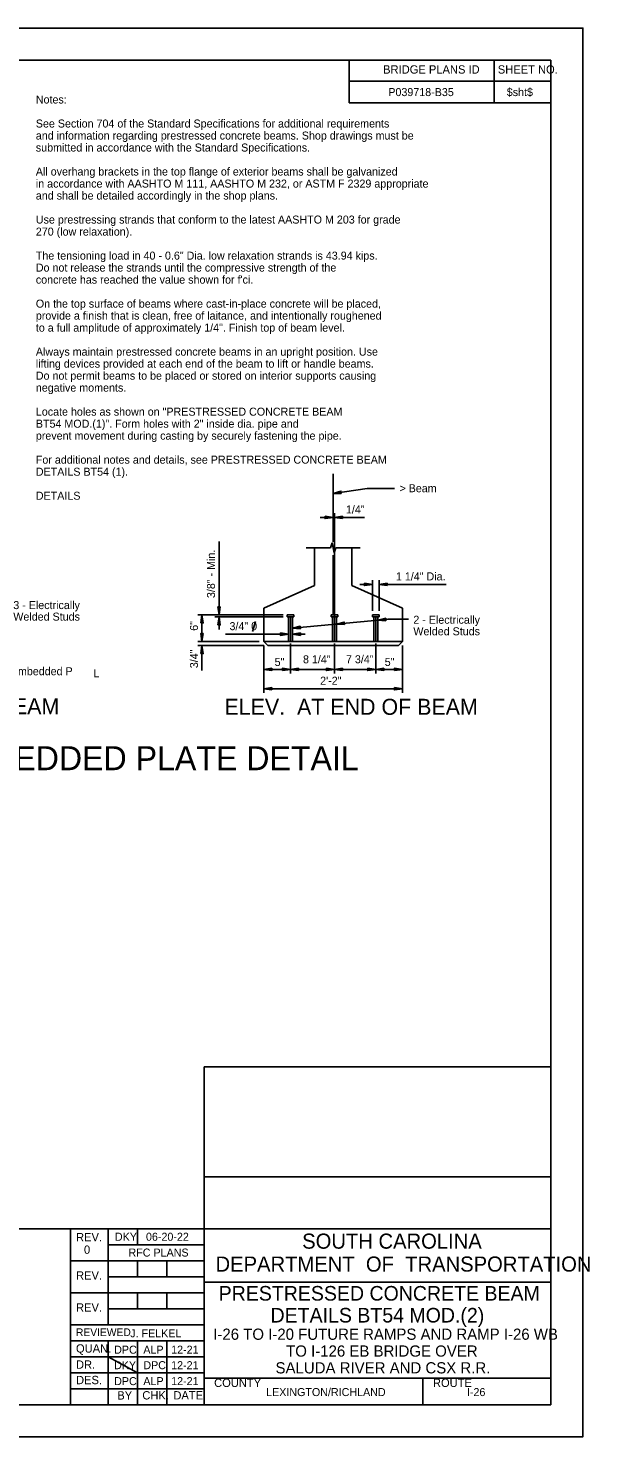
# Model space of a CAD drawing. Extents: x -50.5 to -14.4, y 42.4 to 64.4.
# Drawn here: x -23.18 to -14.41, y 42.45 to 64.45 of the extents above; entities that cross this region are included whole.
import ezdxf

# ---------------------------------------------------------------- set-up
doc = ezdxf.new("R2010")
doc.units = 0
for name, color, linetype in [('BR_AUTO DIMENSION', 7, 'Continuous'), ('BR_BORDER LINES', 7, 'Continuous'), ('BR_CENTER LINES', 7, 'Continuous'), ('BR_PRESTRESSED BEAM', 7, 'Continuous'), ('BR_STRUCTURAL STEEL', 7, 'Continuous'), ('BR_TEXT', 7, 'Continuous'), ('Level 31', 7, 'Continuous')]:
    doc.layers.add(name, color=color, linetype=linetype)

msp = doc.modelspace()

# ---------------------------------------------------------------- linework, layer by layer
at = {"layer": 'BR_AUTO DIMENSION'}
for p, q in [((-18.421, 57.181), (-17.888, 57.259)), ((-17.461, 57.259), (-17.888, 57.259)), ((-18.621, 56.807), (-18.421, 56.807)), ((-18.421, 56.649), (-18.421, 56.872)), ((-18.4, 56.649), (-18.4, 56.872)), ((-17.933, 56.807), (-18.379, 56.807)), ((-20.202, 56.432), (-20.202, 55.286)), ((-18.84, 56.333), (-18.464, 56.333)), ((-18.378, 56.333), (-17.997, 56.333)), ((-18.006, 55.761), (-17.806, 55.761)), ((-17.806, 55.348), (-17.806, 55.826)), ((-17.702, 55.348), (-17.702, 55.826)), ((-16.657, 55.761), (-17.702, 55.761)), ((-19.202, 55.286), (-20.531, 55.286)), ((-20.469, 55.286), (-20.469, 54.869)), ((-19.202, 55.255), (-20.268, 55.255)), ((-20.202, 55.055), (-20.202, 55.255)), ((-20.469, 55.069), (-20.469, 54.869)), ((-19.056, 55.079), (-17.605, 55.214)), ((-17.525, 55.218), (-17.245, 55.218)), ((-19.575, 54.869), (-20.531, 54.869)), ((-19.504, 54.807), (-20.531, 54.807)), ((-20.469, 54.417), (-20.469, 54.807)), ((-20.099, 54.985), (-19.119, 54.985)), ((-19.504, 54.807), (-19.504, 54.07)), ((-19.088, 54.84), (-19.088, 54.372)), ((-18.856, 54.985), (-19.056, 54.985)), ((-18.4, 54.84), (-18.4, 54.372)), ((-17.754, 54.84), (-17.754, 54.372)), ((-17.338, 54.807), (-17.338, 54.07)), ((-19.088, 54.434), (-19.504, 54.434)), ((-19.088, 54.434), (-18.421, 54.434)), ((-18.421, 54.434), (-17.754, 54.434)), ((-17.754, 54.434), (-17.338, 54.434)), ((-19.504, 54.132), (-17.338, 54.132))]:
    msp.add_line(p, q, dxfattribs=at)
for points in [[(-18.295, 57.181), (-18.421, 57.181), (-18.3, 57.218)], [(-18.546, 56.826), (-18.421, 56.807), (-18.546, 56.789)], [(-18.275, 56.789), (-18.4, 56.807), (-18.275, 56.826)], [(-17.931, 55.78), (-17.806, 55.761), (-17.931, 55.743)], [(-17.577, 55.743), (-17.702, 55.761), (-17.577, 55.78)], [(-20.487, 55.161), (-20.469, 55.286), (-20.45, 55.161)], [(-20.183, 55.411), (-20.202, 55.286), (-20.221, 55.411)], [(-20.221, 55.13), (-20.202, 55.255), (-20.183, 55.13)], [(-17.597, 55.195), (-17.723, 55.203), (-17.6, 55.232)], [(-19.244, 55.003), (-19.119, 54.985), (-19.244, 54.966)], [(-18.93, 55.07), (-19.056, 55.079), (-18.933, 55.108)], [(-18.931, 54.966), (-19.056, 54.985), (-18.931, 55.003)], [(-18.243, 55.135), (-18.369, 55.143), (-18.246, 55.172)], [(-20.45, 54.994), (-20.469, 54.869), (-20.487, 54.994)], [(-20.487, 54.682), (-20.469, 54.807), (-20.45, 54.682)], [(-19.379, 54.453), (-19.504, 54.434), (-19.379, 54.416)], [(-19.213, 54.416), (-19.088, 54.434), (-19.213, 54.453)], [(-18.963, 54.416), (-19.088, 54.434), (-18.963, 54.453)], [(-18.525, 54.453), (-18.4, 54.434), (-18.525, 54.416)], [(-18.275, 54.416), (-18.4, 54.434), (-18.275, 54.453)], [(-17.879, 54.453), (-17.754, 54.434), (-17.879, 54.416)], [(-17.629, 54.453), (-17.754, 54.434), (-17.629, 54.416)], [(-17.463, 54.416), (-17.338, 54.434), (-17.463, 54.453)], [(-19.379, 54.114), (-19.504, 54.132), (-19.379, 54.151)], [(-17.463, 54.151), (-17.338, 54.132), (-17.463, 54.114)]]:
    msp.add_lwpolyline(points, close=True, dxfattribs=at)
msp.add_lwpolyline([(-18.464, 56.333), (-18.435, 56.41), (-18.407, 56.256), (-18.378, 56.333)], dxfattribs=at)
msp.add_arc((-17.525, 54.468), 0.75, 90, 96.1252, dxfattribs=at)
at = {"layer": 'BR_BORDER LINES'}
for p, q in [((-15.019, 63.949), (-48.685, 63.949)), ((-18.172, 63.282), (-18.172, 63.949)), ((-15.905, 63.282), (-15.905, 63.949)), ((-15.019, 42.949), (-15.019, 63.949)), ((-18.172, 63.619), (-15.019, 63.619)), ((-15.905, 63.619), (-15.019, 63.619)), ((-15.019, 63.282), (-18.172, 63.282)), ((-20.436, 42.949), (-20.436, 48.225)), ((-20.436, 48.225), (-15.019, 48.225)), ((-20.436, 46.51), (-15.019, 46.51)), ((-27.885, 45.699), (-22.52, 45.699)), ((-22.52, 42.949), (-22.52, 45.699)), ((-22.52, 45.699), (-15.019, 45.699)), ((-21.936, 45.699), (-21.936, 44.199)), ((-21.478, 45.449), (-21.478, 45.699)), ((-21.936, 45.449), (-20.436, 45.449)), ((-22.52, 45.199), (-20.436, 45.199)), ((-21.478, 44.949), (-21.478, 45.199)), ((-21.019, 44.949), (-21.019, 45.199)), ((-21.936, 44.949), (-20.436, 44.949)), ((-22.52, 44.699), (-20.436, 44.699)), ((-21.478, 44.449), (-21.478, 44.699)), ((-21.019, 44.449), (-21.019, 44.699)), ((-20.436, 44.865), (-20.436, 44.865)), ((-20.436, 44.865), (-15.019, 44.865)), ((-21.936, 44.449), (-20.436, 44.449)), ((-22.52, 44.199), (-20.436, 44.199)), ((-22.52, 43.949), (-20.436, 43.949)), ((-21.936, 43.949), (-21.936, 42.949)), ((-21.478, 43.949), (-21.478, 42.949)), ((-21.019, 43.949), (-21.019, 42.949)), ((-22.52, 43.699), (-20.436, 43.699)), ((-22.52, 43.449), (-20.436, 43.449)), ((-20.436, 43.365), (-15.019, 43.365)), ((-20.339, 43.365), (-15.019, 43.365)), ((-17.019, 42.949), (-17.019, 43.365)), ((-22.52, 43.199), (-20.436, 43.199)), ((-48.685, 42.949), (-15.019, 42.949))]:
    msp.add_line(p, q, dxfattribs=at)
at = {"layer": 'BR_CENTER LINES'}
for p, q in [((-18.421, 57.486), (-18.421, 56.426)), ((-18.4, 56.649), (-18.4, 54.869)), ((-18.421, 56.218), (-18.421, 55.286)), ((-19.088, 55.255), (-19.088, 54.869)), ((-17.754, 55.255), (-17.754, 54.869))]:
    msp.add_line(p, q, dxfattribs=at)
at = {"layer": 'BR_PRESTRESSED BEAM'}
for p, q in [((-18.712, 56.333), (-18.712, 55.746)), ((-18.129, 56.333), (-18.129, 55.746)), ((-19.503, 55.39), (-18.713, 55.746)), ((-18.129, 55.746), (-17.338, 55.39)), ((-19.503, 54.869), (-19.503, 55.39)), ((-17.338, 55.39), (-17.338, 54.869))]:
    msp.add_line(p, q, dxfattribs=at)
at = {"layer": 'BR_STRUCTURAL STEEL'}
for p, q in [((-19.14, 55.286), (-19.036, 55.286)), ((-19.14, 55.286), (-19.14, 55.255)), ((-19.14, 55.255), (-19.036, 55.255)), ((-19.119, 55.255), (-19.119, 54.869)), ((-19.056, 55.255), (-19.056, 54.869)), ((-19.036, 55.286), (-19.036, 55.255)), ((-18.452, 55.286), (-18.348, 55.286)), ((-18.452, 55.286), (-18.452, 55.255)), ((-18.452, 55.255), (-18.348, 55.255)), ((-18.431, 55.255), (-18.431, 54.869)), ((-18.369, 55.255), (-18.369, 54.869)), ((-18.348, 55.286), (-18.348, 55.255)), ((-17.806, 55.286), (-17.702, 55.286)), ((-17.806, 55.286), (-17.806, 55.255)), ((-17.806, 55.255), (-17.702, 55.255)), ((-17.786, 55.255), (-17.786, 54.869)), ((-17.723, 55.255), (-17.723, 54.869)), ((-17.702, 55.286), (-17.702, 55.255)), ((-19.504, 54.869), (-17.338, 54.869)), ((-19.442, 54.807), (-19.504, 54.869)), ((-19.442, 54.807), (-17.4, 54.807)), ((-17.4, 54.807), (-17.338, 54.869))]:
    msp.add_line(p, q, dxfattribs=at)
at = {"layer": 'BR_TEXT'}
msp.add_line((-19.632, 55.183), (-19.679, 55.028), dxfattribs=at)
at = {"layer": 'Level 31'}
for p, q in [((-17.727, 44.425), (-17.727, 44.425)), ((-21.936, 43.699), (-21.478, 43.449))]:
    msp.add_line(p, q, dxfattribs=at)
msp.add_lwpolyline([(-50.519, 42.449), (-14.519, 42.449), (-14.519, 64.449), (-50.519, 64.449)], close=True, dxfattribs=at)

# ---------------------------------------------------------------- texts
at = {"layer": 'BR_AUTO DIMENSION'}
for s, p in [(' 1/4"', (-18.267, 56.87)), ('1 1/4" Dia.', (-17.44, 55.824)), ('3/4" 0', (-20.039, 55.047)), ('5"', (-19.334, 54.488)), ('8 1/4"', (-18.891, 54.529)), ('7 3/4"', (-18.22, 54.53)), ('5"', (-17.615, 54.488)), ('2\'-2"', (-18.623, 54.195))]:
    msp.add_text(s, height=0.125, dxfattribs=at).set_placement(p)
for s, p in [('3/8" - Min.', (-20.265, 55.548)), ('6"', (-20.531, 55.037)), ('3/4"', (-20.531, 54.453))]:
    msp.add_text(s, height=0.125, rotation=90, dxfattribs=at).set_placement(p)
at = {"layer": 'BR_TEXT'}
for s, height, p in [('BRIDGE PLANS ID', 0.13, (-17.64, 63.739)), ('SHEET NO.', 0.13, (-15.849, 63.739)), ('Notes:', 0.125, (-23.063, 63.272)), ('P039718-B35', 0.125, (-17.559, 63.388)), ('$sht$', 0.125, (-15.709, 63.388)), ('See Section 704 of the Standard Specifications for additional requirements', 0.125, (-23.063, 62.897)), ('and information regarding prestressed concrete beams. Shop drawings must be ', 0.125, (-23.063, 62.709)), ('submitted in accordance with the Standard Specifications.', 0.125, (-23.063, 62.522)), ('All overhang brackets in the top flange of exterior beams shall be galvanized', 0.125, (-23.063, 62.147)), ('in accordance with AASHTO M 111, AASHTO M 232, or ASTM F 2329 appropriate', 0.125, (-23.063, 61.959)), ('and shall be detailed accordingly in the shop plans.', 0.125, (-23.063, 61.772)), ('Use prestressing strands that conform to the latest AASHTO M 203 for grade', 0.125, (-23.063, 61.397)), ('270 (low relaxation).', 0.125, (-23.063, 61.209)), ('The tensioning load in 40 - 0.6" Dia. low relaxation strands is 43.94 kips.', 0.125, (-23.063, 60.834)), ('Do not release the strands until the compressive strength of the ', 0.125, (-23.063, 60.647)), ("concrete has reached the value shown for f'ci.", 0.125, (-23.063, 60.459)), ('On the top surface of beams where cast-in-place concrete will be placed, ', 0.125, (-23.063, 60.084)), ('to a full amplitude of approximately 1/4". Finish top of beam level.', 0.125, (-23.063, 59.709)), ('provide a finish that is clean, free of laitance, and intentionally roughened ', 0.125, (-23.063, 59.897)), ('Always maintain prestressed concrete beams in an upright position. Use ', 0.125, (-23.063, 59.334)), ('lifting devices provided at each end of the beam to lift or handle beams.', 0.125, (-23.063, 59.147)), ('Do not permit beams to be placed or stored on interior supports causing ', 0.125, (-23.063, 58.959)), ('negative moments.', 0.125, (-23.063, 58.772)), ('Locate holes as shown on "PRESTRESSED CONCRETE BEAM ', 0.125, (-23.063, 58.397)), ('BT54 MOD.(1)". Form holes with 2" inside dia. pipe and', 0.125, (-23.063, 58.209)), ('prevent movement during casting by securely fastening the pipe.', 0.125, (-23.063, 58.022)), ('For additional notes and details, see PRESTRESSED CONCRETE BEAM ', 0.125, (-23.063, 57.647)), ('DETAILS BT54 (1).', 0.125, (-23.063, 57.459)), ('DETAILS', 0.125, (-23.063, 57.084)), ('3 - Electrically', 0.125, (-23.415, 55.376)), ('Welded Studs', 0.125, (-23.415, 55.196)), ('2 - Electrically', 0.125, (-17.168, 55.147)), ('Welded Studs', 0.125, (-17.168, 54.967)), ('beam and bottom of embedded P', 0.125, (-24.969, 54.343)), ('L', 0.125, (-22.165, 54.312)), ('ELEV.  AT SIDE OF BEAM', 0.25, (-26.728, 53.734)), ('ELEV.  AT END OF BEAM', 0.25, (-20.118, 53.725)), ('EMBEDDED PLATE DETAIL', 0.375, (-24.486, 52.86)), ('REV.', 0.13, (-22.435, 45.502)), ('DKY', 0.125, (-21.828, 45.511)), ('06-20-22', 0.125, (-21.343, 45.511)), ('SOUTH CAROLINA', 0.23587, (-18.904, 45.387)), ('0', 0.13, (-22.311, 45.307)), ('RFC PLANS', 0.125, (-21.616, 45.264)), ('DEPARTMENT  OF  TRANSPORTATION', 0.23587, (-20.257, 45.029)), ('REV.', 0.13, (-22.435, 44.904)), ('PRESTRESSED CONCRETE BEAM ', 0.228, (-20.208, 44.576)), ('REV.', 0.13, (-22.435, 44.404)), ('DETAILS BT54 MOD.(2)', 0.228, (-19.398, 44.234)), ('REVIEWED', 0.12, (-22.436, 44.022)), ('J. FELKEL', 0.125, (-21.589, 44.003)), ('I-26 TO I-20 FUTURE RAMPS AND RAMP I-26 WB', 0.175, (-20.293, 43.964)), ('QUAN.', 0.13, (-22.436, 43.764)), ('DPC', 0.125, (-21.84, 43.747)), ('ALP', 0.125, (-21.384, 43.747)), ('12-21', 0.125, (-20.95, 43.747)), ('TO I-126 EB BRIDGE OVER', 0.175, (-19.155, 43.701)), ('DR.', 0.13, (-22.436, 43.512)), ('DKY', 0.125, (-21.841, 43.505)), ('DPC', 0.125, (-21.384, 43.505)), ('12-21', 0.125, (-20.95, 43.505)), ('SALUDA RIVER AND CSX R.R.', 0.175, (-19.32, 43.439)), ('DES.', 0.13, (-22.435, 43.271)), ('DPC', 0.125, (-21.84, 43.256)), ('ALP', 0.125, (-21.384, 43.256)), ('12-21', 0.125, (-20.95, 43.256)), ('COUNTY', 0.13, (-20.279, 43.227)), ('ROUTE', 0.13, (-16.862, 43.227)), ('BY', 0.13, (-21.791, 43.031)), ('CHK.', 0.13, (-21.4, 43.032)), ('DATE', 0.13, (-20.915, 43.032)), ('LEXINGTON/RICHLAND', 0.12499, (-19.467, 43.085)), ('I-26', 0.125, (-16.331, 43.085))]:
    msp.add_text(s, height=height, dxfattribs=at).set_placement(p)
msp.add_text('> Beam', height=0.125, rotation=360, dxfattribs=at).set_placement((-17.385, 57.201))

doc.saveas('drawing.dxf')
